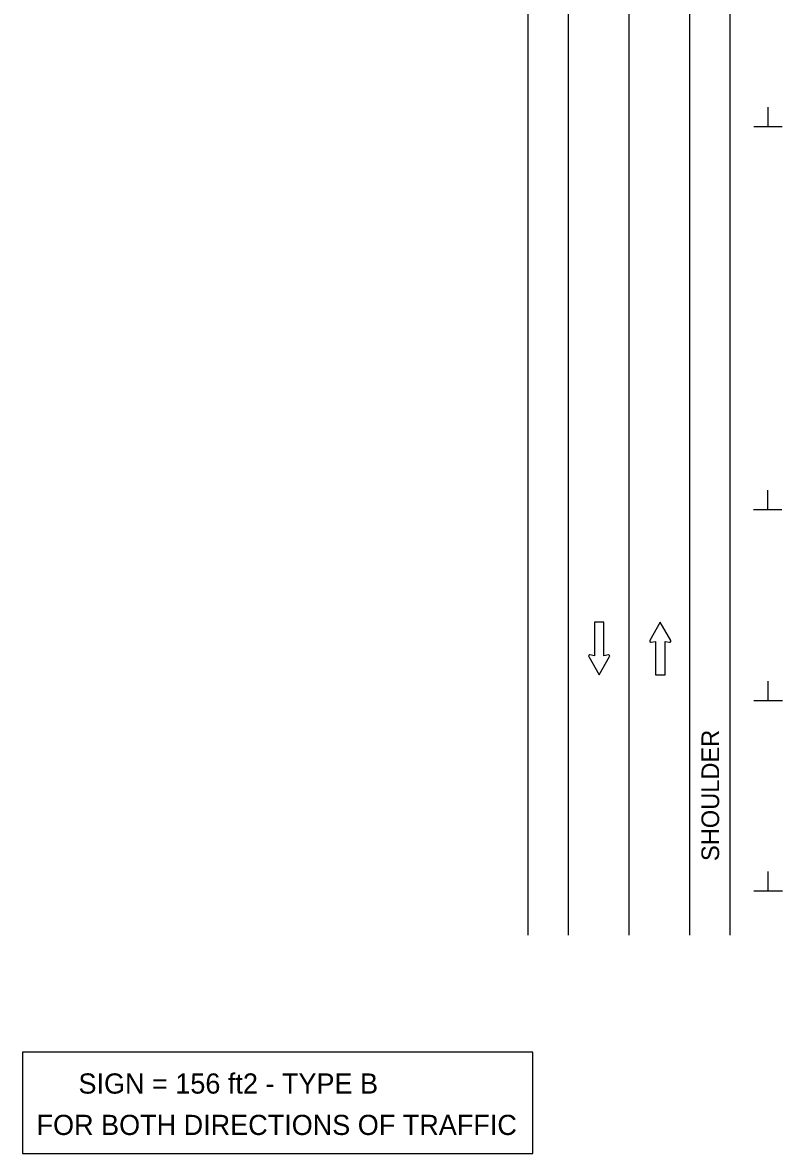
# Model space of a CAD drawing. Extents: x 16734 to 18468, y 5860 to 6911.
# Drawn here: x 16734.1 to 17035, y 5913.1 to 6361.1 of the extents above; entities that cross this region are included whole.
import ezdxf

# ---------------------------------------------------------------- set-up
doc = ezdxf.new("R2010")
doc.units = 0
for name, color, linetype in [('MT_SCRATCH_LEVEL_E', 7, 'Continuous'), ('PAVT_EDGE_EX', 7, 'Continuous'), ('TYPICAL_TEXT_DIMEN_PR', 7, 'Continuous')]:
    doc.layers.add(name, color=color, linetype=linetype)

msp = doc.modelspace()

# ---------------------------------------------------------------- linework, layer by layer
at = {"layer": 'MT_SCRATCH_LEVEL_E'}
for p, q in [((16964.29, 6123.518), (16960.548, 6123.518)), ((16960.548, 6123.518), (16960.548, 6110.26)), ((16964.29, 6123.518), (16960.548, 6123.518)), ((16960.548, 6123.518), (16960.548, 6110.26)), ((16964.29, 6110.26), (16964.29, 6123.518)), ((16964.29, 6110.26), (16964.29, 6123.518)), ((16986.633, 6123.518), (16982.522, 6116.277)), ((16986.633, 6123.518), (16982.522, 6116.277)), ((16990.78, 6116.277), (16986.633, 6123.518)), ((16990.78, 6116.277), (16986.633, 6123.518)), ((16983.004, 6115.593), (16984.781, 6115.909)), ((16983.004, 6115.593), (16984.781, 6115.909)), ((16984.781, 6115.909), (16984.781, 6102.651)), ((16984.781, 6115.909), (16984.781, 6102.651)), ((16988.523, 6102.651), (16988.523, 6115.909)), ((16988.523, 6115.909), (16990.301, 6115.593)), ((16988.523, 6102.651), (16988.523, 6115.909)), ((16988.523, 6115.909), (16990.301, 6115.593)), ((16958.291, 6109.892), (16962.438, 6102.651)), ((16958.291, 6109.892), (16962.438, 6102.651)), ((16960.548, 6110.26), (16958.77, 6110.576)), ((16960.548, 6110.26), (16958.77, 6110.576)), ((16962.438, 6102.651), (16966.549, 6109.892)), ((16962.438, 6102.651), (16966.549, 6109.892)), ((16966.067, 6110.576), (16964.29, 6110.26)), ((16966.067, 6110.576), (16964.29, 6110.26)), ((16984.781, 6102.651), (16988.523, 6102.651)), ((16984.781, 6102.651), (16988.523, 6102.651))]:
    msp.add_line(p, q, dxfattribs=at)
for centre, start, end in [((16982.93, 6116.053), 150.42484, 279.96381), ((16982.93, 6116.053), 150.42484, 279.96381), ((16990.37, 6116.054), 260.03619, 29.77312), ((16990.37, 6116.054), 260.03619, 29.77312), ((16958.701, 6110.115), 80.03619, 209.77312), ((16958.701, 6110.115), 80.03619, 209.77312), ((16966.141, 6110.116), 330.42484, 99.96381), ((16966.141, 6110.116), 330.42484, 99.96381)]:
    msp.add_arc(centre, 0.463, start, end, dxfattribs=at)
at = {"layer": 'PAVT_EDGE_EX'}
for p, q in [((16934.188, 6842.558), (16934.188, 5999.579)), ((16950.188, 6842.558), (16950.188, 5999.579)), ((16998.188, 6842.558), (16998.188, 5999.579)), ((17014.188, 6842.558), (17014.188, 5999.579)), ((16974.188, 6752.987), (16974.188, 5999.579)), ((16974.188, 6752.987), (16974.188, 5999.579))]:
    msp.add_line(p, q, dxfattribs=at)
for points in [[(16974.188, 6352.987), (16974.188, 6327.987)], [(16974.188, 6252.987), (16974.188, 6227.987)], [(16974.188, 6152.987), (16974.188, 6127.987)], [(16974.188, 6052.987), (16974.188, 6027.987)]]:
    msp.add_lwpolyline(points, dxfattribs=at)
at = {"layer": 'TYPICAL_TEXT_DIMEN_PR'}
for p, q in [((17029.32, 6319.856), (17029.32, 6327.641)), ((17029.32, 6319.856), (17023.695, 6319.856)), ((17034.945, 6319.856), (17029.32, 6319.856)), ((17029.154, 6168.025), (17029.154, 6175.81)), ((17029.154, 6168.025), (17023.529, 6168.025)), ((17034.779, 6168.025), (17029.154, 6168.025)), ((17029.345, 6092.357), (17029.345, 6100.142)), ((17029.345, 6092.357), (17023.72, 6092.357)), ((17034.97, 6092.357), (17029.345, 6092.357)), ((17029.345, 6016.965), (17029.345, 6024.75)), ((17029.345, 6016.965), (17023.72, 6016.965)), ((17034.97, 6016.965), (17029.345, 6016.965))]:
    msp.add_line(p, q, dxfattribs=at)
msp.add_lwpolyline([(16734.134, 5913.073), (16936.129, 5913.073), (16936.129, 5953.218), (16734.134, 5953.218)], close=True, dxfattribs=at)

# ---------------------------------------------------------------- texts
msp.add_text('SHOULDER', height=7, rotation=90, dxfattribs=at).set_placement((17009.931, 6028.909))
for s, p in [('SIGN = 156 ft2 - TYPE B', (16756.249, 5936.759)), ('FOR BOTH DIRECTIONS OF TRAFFIC', (16739.649, 5920.361))]:
    msp.add_text(s, height=8, dxfattribs=at).set_placement(p)

doc.saveas('drawing.dxf')
